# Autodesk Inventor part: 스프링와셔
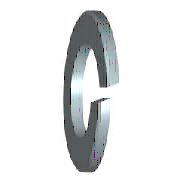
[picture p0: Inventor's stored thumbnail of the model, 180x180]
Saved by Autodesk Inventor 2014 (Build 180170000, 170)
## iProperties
Created: 2012-02
Part Number: 스프링와셔
Material: 강철, 연강
Description: 스프링 와셔
Document SubType Name: Modeling
Standard: JIS B 1251
Designer: mduedu
Standards Organization: JIS
Language: ko-KR
Size Designation: 번호 2 4
Categories: <MemberInstance><Categories><Category DisplayName="조임쇠" InternalName="e4da775c-781d-43d5-af7c-5136215cf5a6" Mnemonic="FSTN"><Category DisplayName="와셔" InternalN
Density: 1 g/cm^3
Appearance: 파란색 - 벽 페인트 - 광택
IsCustomPart: 1
Author: mduedu
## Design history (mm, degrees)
sketch "스케치1"
  geometry: C1 r 3.8 at (0, 0); C2 r 2.05 at (0, 0); 1 further point
  constraints: 2 centre point, 2 coincident
  dimensions: "d0" = 4.1 diameter of C2 (= SD1); "d1" = 7.6 diameter of C1 (= SD2)
extrude "본체" new body sketch "스케치1" distance "d2" = 1 (= SD); taper "d3" = 0 deg
sketch "스케치2"
  geometry: L1 (0, -2.05)-(0, 2.05) reference; L2 (1, 3.8)-(1, -3.8) reference; L3 (-1.2, 0)-(7.2, 0) reference; L4 (0, -0.2)-(1, 0.164); L5 (0, 0.2)-(1, 0.564)
  constraints: 4 end point, 4 point on line, 1 parallel
  dimensions: "d4" = 0.2 distance from line of L3 L4.start (= 0.2 x SD); "d5" = 0.2 distance from line of L3 L5.start (= 0.2 x SD); "d6" = 70 deg angle of L2 L4 (= FAWI)
extrude "절단부" cut sketch "스케치2" stored distance "d7" = 1 (= SD); taper "d8" = 0 deg
workaxis "Work Axis1"
workplane "Work Plane1"
body "Solid1"
other parameters: "SD1" = 4.1 [user parameter; used in 1 equation term], "SD2" = 7.6 [user parameter; used in 1 equation term], "SD" = 1 [user parameter; used in 4 equation terms], "FAWI" = 70 deg [user parameter; used in 1 equation term], "d9" = 0, "d10" = 0, "d11" = 0, "d12" = 0, "SDI" = 1.4 [user parameter], "NND" = 4 [user parameter]
